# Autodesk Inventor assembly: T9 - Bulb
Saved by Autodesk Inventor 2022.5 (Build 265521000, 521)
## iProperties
Created: 2025-02
Part Number: T9 - Bulb
Document SubType Name: Assembly
Designer: AdminForWorker
Title: T9 - Bulb v3
Author: AdminForWorker
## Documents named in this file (2)
- c:\worker\convert-fusion-r06-cosv3\tmp\job-1\19\temp\files\7f12bef2-acc9-47ae-8604-bbc7f61ecf5f\T9 - Bulb v3.iam
- c:\worker\convert-fusion-r06-cosv3\tmp\job-1\19\temp\files\7f12bef2-acc9-47ae-8604-bbc7f61ecf5f\T9 - LED Bulb.iam
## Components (1 placed, 1 different names)
1. T9 - LED Bulb:1 [sub-assembly]
